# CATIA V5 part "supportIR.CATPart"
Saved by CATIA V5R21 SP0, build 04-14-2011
Part number: IR
Bounding box of the stored display mesh (mm): x 0 to 27, y -35.5 to 0, z 0 to 9
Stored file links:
  C:\Users\2027.DESARCY-LEMIE30\Desktop\Assemblage26.05\supportIR.CATPart
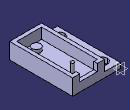
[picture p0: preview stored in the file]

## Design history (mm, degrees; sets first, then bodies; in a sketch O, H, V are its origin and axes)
Body1 (main body)
  Sketch1 on xy-plane, origin (0, 0, 0), H (1, 0, 0), V (0, 1, 0)
    line L1 (0, 0) -> (27, 0)
    line L2 (27, 0) -> (27, -35.5)
    line L3 (27, -35.5) -> (0, -35.5)
    line L4 (0, -35.5) -> (0, 0)
    length L4 = 35.5
    length L1 = 27
    horizontal: L1 H, L3 H
    vertical: L2 V, L4 V
  Pad1: profile Sketch1, direction (0, 0, 1), length 3
  Sketch2 on end face of Pad1, origin (0, 0, 3), H (1, 0, 0), V (0, 1, 0)
    line L1 (9, 0) -> (27, 0)
    line L2 (27, 0) -> (27, -35.5)
    line L3 (27, -35.5) -> (9, -35.5)
    line L4 (9, -35.5) -> (9, 0)
    reference projected line E1 (0, -35.5) -> (27, -35.5) from edge [face of Pad1 from Sketch1.L3 | end face of Pad1]
    reference projected line E2 (27, 0) -> (0, 0) from edge [face of Pad1 from Sketch1.L1 | end face of Pad1]
    reference projected line E3 (27, -35.5) -> (27, 0) from edge [face of Pad1 from Sketch1.L2 | end face of Pad1]
    distance L3 E1 = 0
    distance L1 E2 = 0
    distance L2 E3 = 0
    distance L2 L4 = 18
    horizontal: L1 H, L3 H
    vertical: L2 V, L4 V
  Pad2: profile Sketch2, direction (0, 0, 1), length 6
  Sketch3 on end face of Pad2, origin (0, 0, 9), H (1, 0, 0), V (0, 1, 0)
    line L1 (11, -2) -> (25, -2)
    line L2 (25, -2) -> (25, -33.5)
    line L3 (25, -33.5) -> (11, -33.5)
    line L4 (11, -33.5) -> (11, -2)
    reference projected line E1 (27, 0) -> (9, 0) from edge [face of Pad2 | end face of Pad2]
    reference projected line E2 (9, 0) -> (9, -35.5) from edge [face of Pad2 from Sketch2.L4 | end face of Pad2]
    reference projected line E3 (27, -35.5) -> (27, 0) from edge [face of Pad2 | end face of Pad2]
    reference projected line E4 (9, -35.5) -> (27, -35.5) from edge [face of Pad2 | end face of Pad2]
    distance L1 E1 = 2
    distance L4 E2 = 2
    distance L2 E3 = 2
    distance L3 E4 = 2
    horizontal: L1 H, L3 H
    vertical: L2 V, L4 V
  Pocket1: profile Sketch3, direction (0, 0, -1), length 6
  Sketch4 on end face of Pocket1, origin (0, 0, 3), H (1, 0, 0), V (0, 1, 0)
    circle A1 centre (17.7557, -29.6189) radius 2.5
    radius A1 = 2.5
  Pad3: profile Sketch4, direction (0, 0, 1), length 2
  Sketch5 on end face of Pocket1, origin (0, 0, 3), H (1, 0, 0), V (0, 1, 0)
    circle A1 centre (18.25, -8.75) radius 1
    radius A1 = 1
  Pad4: profile Sketch5, direction (0, 0, 1), length 5
  Sketch6 on end face of Pad1, origin (0, 0, 3), H (1, 0, 0), V (0, 1, 0)
    circle A1 centre (4.5, -5.75) radius 3
    circle A2 centre (4.5, -29.75) radius 3
    radius A1 = 3
  Pocket2: profile Sketch6, direction (0, 0, -1), through (limit type 6)
  Sketch7 on face of Pad2, origin (0, 0, 0), H (-1, 0, 0), V (0, 0, 1)
    line L1 (-23, 9) -> (-13, 9)
    line L2 (-13, 9) -> (-13, 5)
    line L3 (-13, 5) -> (-23, 5)
    line L4 (-23, 5) -> (-23, 9)
    reference projected line E1 (-27, 9) -> (-9, 9) from edge [face of Pad2 | end face of Pad2]
    reference projected line E2 (-9, 3) -> (-9, 9) from edge [face of Pad2 from Sketch2.L4 | face of Pad2]
    reference projected line E3 (-27, 0) -> (-27, 3) from edge [face of Pad2 | face of Pad2]
    length L4 = 4
    distance L2 E2 = 4
    distance E3 L4 = 4
    horizontal: L1 H, L3 H
    vertical: L2 V, L4 V
    coincidence: L1 E1
  Pocket3: profile Sketch7, direction (0, -1, 0), through (limit type 6)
